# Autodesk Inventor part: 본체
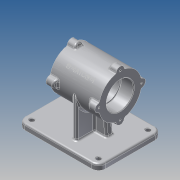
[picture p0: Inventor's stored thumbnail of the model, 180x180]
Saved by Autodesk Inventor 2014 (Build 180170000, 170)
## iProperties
Created: 2015-12
Part Number: 본체
Material: Aluminum 6061
Document SubType Name: Modeling
Designer: user
Density: 2.71 g/cm^3
Appearance: Aluminum - Flat
Mass: 1164.64 g
Surface Area: 814.792 cm^2
Volume: 429.757 cm^3
Author: user
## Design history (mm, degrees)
sketch "Sketch1"
  geometry: C1 r 37 at (0, 0); 1 further point
  constraints: 1 centre point, 1 coincident
  dimensions: "d0" = 74 diameter of C1
extrude "Extrusion1" new body sketch "Sketch1" stored distance "d1" = 85; taper "d2" = 0 deg
workplane "Work Plane1"
sketch "Sketch2"
  geometry: L1 (-37, 0)-(-37, -80); L2 (-37, -80)-(37, -80); L3 (37, 0)-(37, -80); L4 (37, 0)-(-37, 0); A1 r 37 centre (0, 0) between (-37, 0) and (37, 0) reference; 1 further point
  constraints: 8 end point, 2 point on circle
  dimensions: "d3" = 80 distance from line of A1.centre L2
extrude "Extrusion2" join sketch "Sketch2" stored distance "d4" = 8; taper "d5" = 0 deg
sketch "Sketch3"
  geometry: L1 (74, -8)-(74, 0) reference; L2 (0, 0)-(74, 0) reference; L3 (0, -8)-(0, 0) reference; L4 (74, -8)-(0, -8) reference; L5 (-6, 56)-(80, 56); L6 (92, 44)-(92, -72); L7 (80, -84)-(-6, -84); L8 (-18, -72)-(-18, 44); A1 r 12 centre (80, 44) between (92, 44) and (80, 56); A2 r 12 centre (-6, 44) between (-6, 56) and (-18, 44); A3 r 12 centre (-6, -72) between (-18, -72) and (-6, -84); A4 r 12 centre (80, -72) between (80, -84) and (92, -72); 5 further points
  constraints: 8 end point, 8 point on circle, 8 point on line, 8 tangent, 4 centre point, 3 equal radius
  dimensions: "d6" = 140 distance between parallel lines of L7 L5; "d7" = 110 distance between parallel lines of L8 L6; "d10" = 80 distance from line of L7 point (37, -4); "d11" = 55 distance from line of L8 point (37, -4); "d14" = 12 radius of A1
extrude "Extrusion3" join sketch "Sketch3" distance "d12" = 10; taper "d13" = 0 deg
sketch "Sketch4"
  geometry: C1 r 4 at (0, -12); C2 r 4 at (86, -12); C3 r 4 at (86, -128); C4 r 4 at (0, -128); A1 r 12 centre (86, -12) between (98, -12) and (86, 0) reference; A2 r 12 centre (0, -12) between (0, 0) and (-12, -12) reference; A3 r 12 centre (0, -128) between (-12, -128) and (0, -140) reference; A4 r 12 centre (86, -128) between (86, -140) and (98, -128) reference; 1 further point
  constraints: 4 centre point, 4 coincident
  dimensions: "d15" = 8 diameter of C1; "d16" = 8 diameter of C2; "d17" = 8 diameter of C4; "d18" = 8 diameter of C3
extrude "Extrusion4" cut sketch "Sketch4" distance "d19" = 10; taper "d20" = 0 deg
workplane "Work Plane2"
sketch "Sketch5"
  geometry: L1 (-38.5, -37)-(-38.5, 37) reference; L2 (-38.5, 37)-(46.5, 37) reference; L3 (46.5, 37)-(46.5, -37) reference; L4 (46.5, -37)-(8, -37) reference; L5 (8, -37)-(8, -70) reference; L6 (8, -70)-(64, -70) reference; L7 (64, -70)-(64, -80) reference; L8 (64, -80)-(-76, -80) reference; L9 (-76, -80)-(-76, -70) reference; L10 (-76, -70)-(0, -70) reference; L11 (0, -70)-(0, -37) reference; L12 (0, -37)-(-38.5, -37) reference; L13 (29, -70)-(21.765, -11.077); L14 (-21, -70)-(-14.851, -19.921); L15 (-14.851, -19.921)-(21.765, -11.077); L16 (0, -55.098)-(8, -55.098); L17 (4, -55.098)-(4, -48.353); L18 (29, -70)-(-21, -70); 1 further point
  constraints: 12 end point, 4 point on line, 1 midpoint
  dimensions: "d21" = 25 distance from line of L14.start L17; "d22" = 50 distance of L13.start L14.start; "d23" = 97 deg angle of L10 L14; "d24" = 97 deg angle of L6 L13; "d25" = 90 deg angle of L16 L17
extrude "Extrusion5" join sketch "Sketch5" stored distance "d26" = 12; taper "d27" = 0 deg
sketch "Sketch6"
  geometry: C1 r 7 at (0, 37); 1 further point
  constraints: 1 centre point, 1 vertical alignment, 1 other
  dimensions: "d28" = 14 diameter of C1
extrude "Extrusion6" join sketch "Sketch6" distance "d29" = 12; taper "d30" = 0 deg
sketch "Sketch7"
  geometry: L1 (-16.948, -37)-(-38.5, -37) reference; L2 (-38.5, -37)-(-38.5, 37) reference; L3 (-38.5, 37)-(34.5, 37) reference; L4 (34.5, 37)-(34.5, 44) reference; L5 (34.5, 44)-(46.5, 44) reference; L6 (46.5, 44)-(46.5, -37) reference; L7 (46.5, -37)-(24.948, -37) reference; L8 (24.948, -37)-(29, -70) reference; L9 (29, -70)-(64, -70) reference; L10 (64, -70)-(64, -80) reference; L11 (64, -80)-(-76, -80) reference; L12 (-76, -80)-(-76, -70) reference; L13 (-76, -70)-(-21, -70) reference; L14 (-21, -70)-(-16.948, -37) reference; L15 (34.5, 44)-(29.154, 29.313); L16 (29.154, 29.313)-(34.5, 29.313); L17 (34.5, 29.313)-(34.5, 44); 1 further point
  constraints: 6 end point
  dimensions: "d31" = 110 deg angle of L3 L15
extrude "Extrusion7" join sketch "Sketch7" stored distance "d32" = 14; taper "d33" = 0 deg
sketch "Sketch8"
  geometry: L1 (-11.136, 35.284)-(-11.908, 49.217); L2 (-11.908, 49.217)-(13.943, 48.14); L3 (13.943, 48.14)-(11.136, 35.284); A1 r 37 centre (0, 0) between (-6.969, 36.338) and (6.969, 36.338) reference; A2 r 7 centre (0, 37) between (6.969, 36.338) and (-6.969, 36.338) reference
  constraints: 6 end point, 2 point on circle
extrude "Extrusion8" cut sketch "Sketch8" distance "d34" = 19; taper "d35" = 0 deg
pattern_circular "Circular Pattern1" dims "d37" = 360 deg
workplane "Work Plane3"
mirror "Mirror1"
sketch "Sketch9"
  geometry: C1 r 23.5 at (0, 0); A1 r 37 centre (0, 0) between (6.969, -36.338) and (36.338, -6.969) reference
  constraints: 1 centre point, 1 coincident
  dimensions: "d39" = 47 diameter of C1
extrude "Extrusion9" cut sketch "Sketch9" distance "d40" = 22; taper "d41" = 0 deg
sketch "Sketch10"
  geometry: C1 r 23.5 at (0, 0) reference; C2 r 21 at (0, 0)
  constraints: 1 centre point, 1 coincident
  dimensions: "d42" = 42 diameter of C2
extrude "Extrusion10" cut sketch "Sketch10" distance "d43" = 41; taper "d44" = 0 deg
sketch "Sketch11"
  geometry: C1 r 23.5 at (0, 0); A1 r 37 centre (0, 0) between (-6.969, 36.338) and (-36.338, 6.969) reference
  constraints: 1 centre point, 1 coincident
  dimensions: "d45" = 47 diameter of C1
extrude "Extrusion11" cut sketch "Sketch11" distance "d46" = 22; taper "d47" = 0 deg
fillet "Fillet1" dims "d48" = 0.3
chamfer "Chamfer1" distance "d49" = 1; stored, may be unused: second distance "d50" = 2, angle "d51" = 45 deg
sketch "Sketch12"
  geometry: A1 r 7 centre (0, 37) between (6.969, 36.338) and (-6.969, 36.338) reference; A2 r 7 centre (-37, 0) between (-36.338, 6.969) and (-36.338, -6.969) reference; A3 r 7 centre (0, -37) between (-6.969, -36.338) and (6.969, -36.338) reference; A4 r 7 centre (37, 0) between (36.338, -6.969) and (36.338, 6.969) reference
hole "Hole1" sketch "Sketch12" at (0, 37), (37, 0), (0, -37), (-37, 0) diameter "d52" = 3.242; stored, may be unused: countersink angle "d56" = 90 deg, drill point angle "d58" = 118 deg; dims "d53" = 9, "d54" = 4, "d55" = 2, "d57" = 11
mirror "Mirror2"
chamfer "Chamfer2" distance "d59" = 1; stored, may be unused: second distance "d60" = 2, angle "d61" = 45 deg
fillet "Fillet2" dims "d62" = 3
workplane "Work Plane6"
  workplane "Work Plane5"
sketch "Sketch13"
  geometry: 2 further points
  constraints: 1 coincident, 1 other
emboss "Emboss1" sketch "Sketch13" dims "d64" = 0.5, "d65" = 0
fillet "Fillet3" dims "d66" = 3
mirror "Mirror3"
fillet "Fillet4" dims "d67" = 3
fillet "Fillet5" dims "d68" = 3
sketch "Sketch14"
  geometry: L1 (-52, -70)-(52, -70) reference; L2 (55, -73)-(55, -80) reference; L3 (55, -80)-(-55, -80) reference; L4 (-55, -80)-(-55, -73) reference; L5 (-22.375, 30.516)-(-29.63, 23.262); L6 (-43, -73)-(43, -73) reference; L7 (-29.63, 23.262)-(-31.076, 28.119); L8 (-31.076, 28.119)-(-22.375, 30.516); C1 r 1.621 at (0, -37) reference; C2 r 1.621 at (0, 37) reference; C3 r 1.621 at (37, 0) reference; C4 r 1.621 at (-37, 0) reference; C5 r 24.5 at (0, 0) reference; A1 r 37 centre (0, 0) between (-9.104, 35.863) and (-35.863, 9.104) reference; A2 r 37 centre (0, 0) between (35.863, 9.104) and (9.104, 35.863) reference; A3 r 3 centre (38.77, 9.842) between (35.863, 9.104) and (38.239, 6.889) reference; A4 r 7 centre (37, 0) between (38.239, -6.889) and (38.239, 6.889) reference; A5 r 3 centre (38.77, -9.842) between (38.239, -6.889) and (35.863, -9.104) reference; A6 r 37 centre (0, 0) between (9.104, -35.863) and (35.863, -9.104) reference; A7 r 3 centre (9.842, -38.77) between (9.104, -35.863) and (6.889, -38.239) reference; A8 r 7 centre (0, -37) between (-6.889, -38.239) and (6.889, -38.239) reference; A9 r 3 centre (-9.842, -38.77) between (-6.889, -38.239) and (-9.104, -35.863) reference; A10 r 37 centre (0, 0) between (-35.863, -9.104) and (-9.104, -35.863) reference; A11 r 3 centre (-38.77, -9.842) between (-35.863, -9.104) and (-38.239, -6.889) reference; A12 r 7 centre (-37, 0) between (-38.239, 6.889) and (-38.239, -6.889) reference; A13 r 3 centre (-38.77, 9.842) between (-38.239, 6.889) and (-35.863, 9.104) reference; A14 r 37 centre (0, 0) between (-9.104, 35.863) and (-35.863, 9.104) reference; A15 r 3 centre (-9.842, 38.77) between (-9.104, 35.863) and (-6.889, 38.239) reference; A16 r 7 centre (0, 37) between (6.889, 38.239) and (-6.889, 38.239) reference; A17 r 3 centre (9.842, 38.77) between (6.889, 38.239) and (9.104, 35.863) reference; A18 r 3 centre (52, -73) between (55, -73) and (52, -70) reference; A19 r 3 centre (-52, -73) between (-52, -70) and (-55, -73) reference
  constraints: 6 end point
  dimensions: "d69" = 45 deg angle of L5 L6; "d70" = 0.4 distance edge to line of A1 L5
extrude "Extrusion12" cut sketch "Sketch14" distance "d71" = 19.5; taper "d72" = 0 deg
body "Solid1"
node "Project Cut Edges1"
node "Project Cut Edges2"
node "Project Cut Edges3"
node "Project Cut Edges4"
